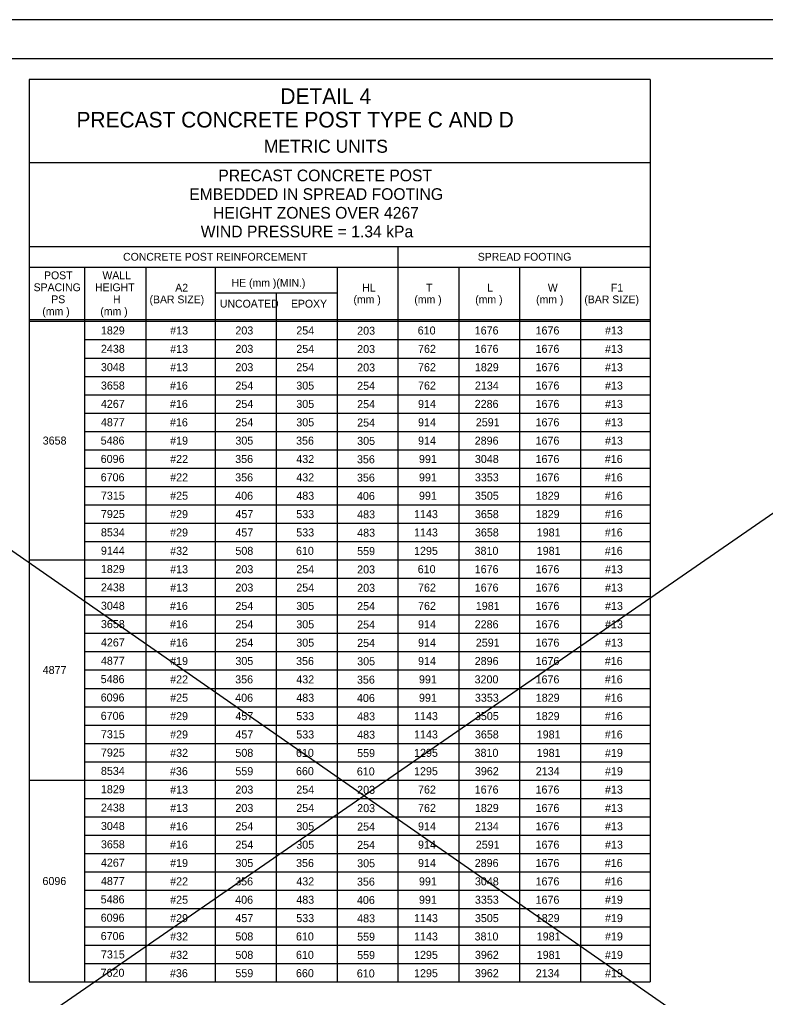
# Model space of a CAD drawing. Extents: x 3351 to 8430, y -3586 to 1457.
# Drawn here: x 7415 to 7700.9, y -2179.4 to -1804.3 of the extents above; entities that cross this region are included whole.
import ezdxf

# ---------------------------------------------------------------- set-up
doc = ezdxf.new("R2010")
doc.units = 0
for name, color, linetype in [('1', 7, 'Continuous'), ('2', 7, 'Continuous'), ('PLT-BNDY', 7, 'Continuous')]:
    doc.layers.add(name, color=color, linetype=linetype)

msp = doc.modelspace()

# ---------------------------------------------------------------- linework, layer by layer
at = {"layer": '1'}
for p, q in [((7144.64, -1822.02), (7933.07, -2370.51)), ((7418.68, -1827.31), (7418.68, -2173.5)), ((7656.68, -1827.31), (7418.68, -1827.31)), ((7656.68, -1827.31), (7656.68, -2173.5)), ((7152.2, -2374.96), (7937.23, -1832.15)), ((7656.68, -1859.31), (7418.68, -1859.31)), ((7418.68, -1891.31), (7656.68, -1891.31)), ((7560.01, -1891.31), (7560.01, -2173.5)), ((7418.68, -1899.31), (7486.68, -1899.31)), ((7418.68, -1899.31), (7656.68, -1899.31)), ((7440.01, -2173.5), (7440.01, -1899.31)), ((7463.34, -1899.31), (7463.34, -2173.5)), ((7490.01, -1899.31), (7490.01, -2173.5)), ((7536.68, -1899.31), (7536.68, -2173.5)), ((7583.34, -1899.31), (7583.34, -2173.5)), ((7606.68, -1899.31), (7606.68, -2173.5)), ((7630.01, -1899.31), (7630.01, -2173.5)), ((7536.71, -1909.31), (7490.05, -1909.31)), ((7513.34, -1909.31), (7513.34, -2173.5)), ((7418.68, -1919.31), (7656.68, -1919.31)), ((7418.68, -1920.06), (7656.68, -1920.06)), ((7476.68, -1923.58), (7476.68, -1923.58)), ((7501.68, -1923.58), (7501.68, -1923.58)), ((7525.01, -1923.58), (7525.01, -1923.58)), ((7548.34, -1923.58), (7548.34, -1923.58)), ((7571.68, -1923.58), (7571.68, -1923.58)), ((7595.01, -1923.58), (7595.01, -1923.58)), ((7618.34, -1923.58), (7618.34, -1923.58)), ((7643.34, -1923.58), (7643.34, -1923.58)), ((7440.01, -1927.1), (7656.68, -1927.1)), ((7440.01, -1934.14), (7656.68, -1934.14)), ((7440.01, -1941.18), (7656.68, -1941.18)), ((7440.01, -1948.22), (7656.68, -1948.22)), ((7440.01, -1955.26), (7656.68, -1955.26)), ((7440.01, -1962.3), (7656.68, -1962.3)), ((7440.01, -1969.34), (7656.68, -1969.34)), ((7440.01, -1976.38), (7656.68, -1976.38)), ((7440.01, -1983.42), (7656.68, -1983.42)), ((7440.01, -1990.46), (7656.68, -1990.46)), ((7440.01, -1997.5), (7656.68, -1997.5)), ((7440.01, -2004.54), (7656.68, -2004.54)), ((7418.68, -2011.58), (7656.68, -2011.58)), ((7418.68, -2011.58), (7656.68, -2011.58)), ((7476.68, -2015.1), (7476.68, -2015.1)), ((7501.68, -2015.1), (7501.68, -2015.1)), ((7525.01, -2015.1), (7525.01, -2015.1)), ((7548.34, -2015.1), (7548.34, -2015.1)), ((7571.68, -2015.1), (7571.68, -2015.1)), ((7595.01, -2015.1), (7595.01, -2015.1)), ((7618.34, -2015.1), (7618.34, -2015.1)), ((7643.34, -2015.1), (7643.34, -2015.1)), ((7440.01, -2018.62), (7656.68, -2018.62)), ((7440.01, -2025.66), (7656.68, -2025.66)), ((7440.01, -2032.7), (7656.68, -2032.7)), ((7440.01, -2039.74), (7656.68, -2039.74)), ((7440.01, -2046.78), (7656.68, -2046.78)), ((7440.01, -2053.82), (7656.68, -2053.82)), ((7440.01, -2060.86), (7656.68, -2060.86)), ((7440.01, -2067.9), (7656.68, -2067.9)), ((7440.01, -2074.94), (7656.68, -2074.94)), ((7440.01, -2081.98), (7656.68, -2081.98)), ((7440.01, -2089.02), (7656.68, -2089.02)), ((7418.68, -2096.06), (7656.68, -2096.06)), ((7476.68, -2099.58), (7476.68, -2099.58)), ((7501.68, -2099.58), (7501.68, -2099.58)), ((7525.01, -2099.58), (7525.01, -2099.58)), ((7548.34, -2099.58), (7548.34, -2099.58)), ((7571.68, -2099.58), (7571.68, -2099.58)), ((7595.01, -2099.58), (7595.01, -2099.58)), ((7618.34, -2099.58), (7618.34, -2099.58)), ((7643.34, -2099.58), (7643.34, -2099.58)), ((7440.01, -2103.1), (7656.68, -2103.1)), ((7440.01, -2110.14), (7656.68, -2110.14)), ((7440.01, -2117.18), (7656.68, -2117.18)), ((7440.01, -2124.22), (7656.68, -2124.22)), ((7440.01, -2131.26), (7656.68, -2131.26)), ((7440.01, -2138.3), (7656.68, -2138.3)), ((7440.01, -2145.34), (7656.68, -2145.34)), ((7440.01, -2152.38), (7656.68, -2152.38)), ((7440.01, -2159.42), (7656.68, -2159.42)), ((7440.01, -2166.46), (7656.68, -2166.46)), ((7418.68, -2173.5), (7656.68, -2173.5))]:
    msp.add_line(p, q, dxfattribs=at)
at = {"layer": '2'}
msp.add_line((7165.34, -1819.31), (7951.34, -1819.31), dxfattribs=at)
at = {"layer": 'PLT-BNDY'}
msp.add_lwpolyline([(7125.34, -1804.31), (7966.34, -1804.31), (7966.34, -2398.31), (7125.34, -2398.31)], close=True, dxfattribs=at)

# ---------------------------------------------------------------- texts
at = {"layer": '1'}
for s, height, p in [('DETAIL 4', 6, (7514.97, -1836.71)), ('PRECAST CONCRETE POST TYPE C AND D', 6, (7436.81, -1845.71)), ('METRIC UNITS', 5, (7508.64, -1855.41)), ('PRECAST CONCRETE POST', 4.5, (7491.19, -1866.36)), ('EMBEDDED IN SPREAD FOOTING', 4.5, (7480.03, -1873.52)), ('HEIGHT ZONES OVER 4267', 4.5, (7489.15, -1880.69)), ('WIND PRESSURE = 1.34 kPa', 4.5, (7484.44, -1887.86)), ('CONCRETE POST REINFORCEMENT', 3, (7454.68, -1896.81)), ('SPREAD FOOTING', 3, (7590.63, -1896.81)), ('POST', 3, (7424.4, -1903.91)), ('WALL', 3, (7446.76, -1903.91)), ('SPACING', 3, (7420.4, -1908.51)), ('HEIGHT', 3, (7443.93, -1908.51)), ('A2', 3, (7474.67, -1908.67)), ('HE (mm )(MIN.)', 3, (7496.27, -1906.8)), ('HL', 3, (7546.31, -1908.67)), ('T', 3, (7570.82, -1908.67)), ('L', 3, (7594.27, -1908.67)), ('W', 3, (7617.48, -1908.67)), ('F1', 3, (7641.64, -1908.67)), ('PS', 3, (7427.16, -1913.11)), ('H', 3, (7450.81, -1913.11)), ('(BAR SIZE)', 3, (7464.81, -1913.17)), ('UNCOATED', 3, (7491.8, -1914.8)), ('EPOXY', 3, (7519.03, -1914.8)), ('(mm )', 3, (7542.98, -1913.17)), ('(mm )', 3, (7566.31, -1913.17)), ('(mm )', 3, (7589.65, -1913.17)), ('(mm )', 3, (7612.98, -1913.17)), ('(BAR SIZE)', 3, (7631.47, -1913.17)), ('(mm )', 3, (7423.73, -1917.71)), ('(mm )', 3, (7445.96, -1917.71)), ('1829', 3.07, (7446.18, -1925.11)), ('#13', 3.07, (7472.73, -1925.11)), ('203', 3.07, (7497.73, -1925.11)), ('254', 3.07, (7521.07, -1925.11)), ('203', 3.07, (7544.4, -1925.21)), ('610', 3.07, (7567.6, -1925.11)), ('1676', 3.07, (7589.45, -1925.11)), ('1676', 3.07, (7612.78, -1925.11)), ('#13', 3.07, (7639.4, -1925.11)), ('2438', 3.07, (7446.19, -1932.15)), ('#13', 3.07, (7472.73, -1932.16)), ('203', 3.07, (7497.73, -1932.16)), ('254', 3.07, (7521.07, -1932.16)), ('203', 3.07, (7544.4, -1932.25)), ('762', 3.07, (7567.73, -1932.16)), ('1676', 3.07, (7589.45, -1932.16)), ('1676', 3.07, (7612.78, -1932.16)), ('#13', 3.07, (7639.4, -1932.16)), ('3048', 3.07, (7446.19, -1939.19)), ('#13', 3.07, (7472.73, -1939.2)), ('203', 3.07, (7497.73, -1939.2)), ('254', 3.07, (7521.07, -1939.2)), ('203', 3.07, (7544.4, -1939.3)), ('762', 3.07, (7567.73, -1939.2)), ('1829', 3.07, (7589.52, -1939.2)), ('1676', 3.07, (7612.78, -1939.2)), ('#13', 3.07, (7639.4, -1939.2)), ('3658', 3.07, (7446.19, -1946.23)), ('#16', 3.07, (7472.65, -1946.25)), ('254', 3.07, (7497.73, -1946.25)), ('305', 3.07, (7521.07, -1946.25)), ('762', 3.07, (7567.73, -1946.25)), ('2134', 3.07, (7589.53, -1946.25)), ('1676', 3.07, (7612.78, -1946.25)), ('#13', 3.07, (7639.4, -1946.25)), ('254', 3.07, (7544.4, -1946.34)), ('4267', 3.07, (7446.19, -1953.27)), ('#16', 3.07, (7472.65, -1953.29)), ('254', 3.07, (7497.73, -1953.29)), ('305', 3.07, (7521.07, -1953.29)), ('254', 3.07, (7544.4, -1953.38)), ('914', 3.07, (7567.73, -1953.29)), ('2286', 3.07, (7589.45, -1953.29)), ('1676', 3.07, (7612.78, -1953.29)), ('#13', 3.07, (7639.4, -1953.29)), ('4877', 3.07, (7446.19, -1960.31)), ('#16', 3.07, (7472.65, -1960.34)), ('254', 3.07, (7497.73, -1960.34)), ('305', 3.07, (7521.07, -1960.34)), ('254', 3.07, (7544.4, -1960.43)), ('914', 3.07, (7567.73, -1960.34)), ('2591', 3.07, (7589.88, -1960.34)), ('1676', 3.07, (7612.78, -1960.34)), ('#13', 3.07, (7639.4, -1960.34)), ('3658', 3.07, (7423.87, -1967.35)), ('5486', 3.07, (7446.1, -1967.35)), ('#19', 3.07, (7472.72, -1967.38)), ('305', 3.07, (7497.73, -1967.38)), ('356', 3.07, (7520.98, -1967.38)), ('305', 3.07, (7544.4, -1967.47)), ('914', 3.07, (7567.73, -1967.38)), ('2896', 3.07, (7589.45, -1967.38)), ('1676', 3.07, (7612.78, -1967.38)), ('#13', 3.07, (7639.4, -1967.38)), ('6096', 3.07, (7446.1, -1974.39)), ('#22', 3.07, (7472.73, -1974.42)), ('356', 3.07, (7497.65, -1974.42)), ('432', 3.07, (7521.07, -1974.42)), ('356', 3.07, (7544.32, -1974.52)), ('991', 3.07, (7568.09, -1974.42)), ('3048', 3.07, (7589.53, -1974.42)), ('1676', 3.07, (7612.78, -1974.42)), ('#16', 3.07, (7639.32, -1974.42)), ('6706', 3.07, (7446.1, -1981.43)), ('#22', 3.07, (7472.73, -1981.47)), ('356', 3.07, (7497.65, -1981.47)), ('432', 3.07, (7521.07, -1981.47)), ('356', 3.07, (7544.32, -1981.56)), ('991', 3.07, (7568.09, -1981.47)), ('3353', 3.07, (7589.53, -1981.47)), ('1676', 3.07, (7612.78, -1981.47)), ('#16', 3.07, (7639.32, -1981.47)), ('7315', 3.07, (7446.19, -1988.47)), ('#25', 3.07, (7472.73, -1988.51)), ('406', 3.07, (7497.65, -1988.51)), ('483', 3.07, (7521.07, -1988.51)), ('406', 3.07, (7544.32, -1988.61)), ('991', 3.07, (7568.09, -1988.51)), ('3505', 3.07, (7589.53, -1988.51)), ('1829', 3.07, (7612.85, -1988.51)), ('#16', 3.07, (7639.32, -1988.51)), ('7925', 3.07, (7446.19, -1995.51)), ('#29', 3.07, (7472.72, -1995.56)), ('457', 3.07, (7497.73, -1995.56)), ('533', 3.07, (7521.07, -1995.56)), ('483', 3.07, (7544.4, -1995.65)), ('1143', 3.07, (7566.2, -1995.56)), ('3658', 3.07, (7589.53, -1995.56)), ('1829', 3.07, (7612.85, -1995.56)), ('#16', 3.07, (7639.32, -1995.56)), ('8534', 3.07, (7446.19, -2002.55)), ('#29', 3.07, (7472.72, -2002.6)), ('457', 3.07, (7497.73, -2002.6)), ('533', 3.07, (7521.07, -2002.6)), ('483', 3.07, (7544.4, -2002.7)), ('1143', 3.07, (7566.2, -2002.6)), ('3658', 3.07, (7589.53, -2002.6)), ('1981', 3.07, (7613.22, -2002.6)), ('#16', 3.07, (7639.32, -2002.6)), ('9144', 3.07, (7446.19, -2009.59)), ('#32', 3.07, (7472.73, -2009.65)), ('508', 3.07, (7497.73, -2009.65)), ('610', 3.07, (7520.94, -2009.65)), ('559', 3.07, (7544.39, -2009.74)), ('1295', 3.07, (7566.2, -2009.65)), ('3810', 3.07, (7589.4, -2009.65)), ('1981', 3.07, (7613.22, -2009.65)), ('#16', 3.07, (7639.32, -2009.65)), ('1829', 3.07, (7446.18, -2016.63)), ('#13', 3.07, (7472.73, -2016.69)), ('203', 3.07, (7497.73, -2016.69)), ('254', 3.07, (7521.07, -2016.69)), ('203', 3.07, (7544.4, -2016.79)), ('610', 3.07, (7567.6, -2016.69)), ('1676', 3.07, (7589.45, -2016.69)), ('1676', 3.07, (7612.78, -2016.69)), ('#13', 3.07, (7639.4, -2016.69)), ('2438', 3.07, (7446.19, -2023.67)), ('#13', 3.07, (7472.73, -2023.74)), ('203', 3.07, (7497.73, -2023.74)), ('254', 3.07, (7521.07, -2023.74)), ('203', 3.07, (7544.4, -2023.83)), ('762', 3.07, (7567.73, -2023.74)), ('1676', 3.07, (7589.45, -2023.74)), ('1676', 3.07, (7612.78, -2023.74)), ('#13', 3.07, (7639.4, -2023.74)), ('3048', 3.07, (7446.19, -2030.71)), ('#16', 3.07, (7472.65, -2030.78)), ('254', 3.07, (7497.73, -2030.78)), ('305', 3.07, (7521.07, -2030.78)), ('254', 3.07, (7544.4, -2030.87)), ('762', 3.07, (7567.73, -2030.78)), ('1981', 3.07, (7589.88, -2030.78)), ('1676', 3.07, (7612.78, -2030.78)), ('#13', 3.07, (7639.4, -2030.78)), ('3658', 3.07, (7446.19, -2037.75)), ('#16', 3.07, (7472.65, -2037.82)), ('254', 3.07, (7497.73, -2037.82)), ('305', 3.07, (7521.07, -2037.82)), ('254', 3.07, (7544.4, -2037.92)), ('914', 3.07, (7567.73, -2037.82)), ('2286', 3.07, (7589.45, -2037.82)), ('1676', 3.07, (7612.78, -2037.82)), ('#13', 3.07, (7639.4, -2037.82)), ('4267', 3.07, (7446.19, -2044.79)), ('#16', 3.07, (7472.65, -2044.87)), ('254', 3.07, (7497.73, -2044.87)), ('305', 3.07, (7521.07, -2044.87)), ('254', 3.07, (7544.4, -2044.96)), ('914', 3.07, (7567.73, -2044.87)), ('2591', 3.07, (7589.88, -2044.87)), ('1676', 3.07, (7612.78, -2044.87)), ('#13', 3.07, (7639.4, -2044.87)), ('4877', 3.07, (7446.19, -2051.83)), ('#19', 3.07, (7472.72, -2051.91)), ('305', 3.07, (7497.73, -2051.91)), ('356', 3.07, (7520.98, -2051.91)), ('305', 3.07, (7544.4, -2052.01)), ('914', 3.07, (7567.73, -2051.91)), ('2896', 3.07, (7589.45, -2051.91)), ('1676', 3.07, (7612.78, -2051.91)), ('#16', 3.07, (7639.32, -2051.91)), ('4877', 3.07, (7423.87, -2055.35)), ('5486', 3.07, (7446.1, -2058.87)), ('#22', 3.07, (7472.73, -2058.96)), ('356', 3.07, (7497.65, -2058.96)), ('432', 3.07, (7521.07, -2058.96)), ('356', 3.07, (7544.32, -2059.05)), ('991', 3.07, (7568.09, -2058.96)), ('3200', 3.07, (7589.4, -2058.96)), ('1676', 3.07, (7612.78, -2058.96)), ('#16', 3.07, (7639.32, -2058.96)), ('6096', 3.07, (7446.1, -2065.91)), ('#25', 3.07, (7472.73, -2066)), ('406', 3.07, (7497.65, -2066)), ('483', 3.07, (7521.07, -2066)), ('406', 3.07, (7544.32, -2066.1)), ('991', 3.07, (7568.09, -2066)), ('3353', 3.07, (7589.53, -2066)), ('1829', 3.07, (7612.85, -2066)), ('#16', 3.07, (7639.32, -2066)), ('6706', 3.07, (7446.1, -2072.95)), ('#29', 3.07, (7472.72, -2073.05)), ('457', 3.07, (7497.73, -2073.05)), ('533', 3.07, (7521.07, -2073.05)), ('483', 3.07, (7544.4, -2073.14)), ('1143', 3.07, (7566.2, -2073.05)), ('3505', 3.07, (7589.53, -2073.05)), ('1829', 3.07, (7612.85, -2073.05)), ('#16', 3.07, (7639.32, -2073.05)), ('7315', 3.07, (7446.19, -2079.99)), ('#29', 3.07, (7472.72, -2080.09)), ('457', 3.07, (7497.73, -2080.09)), ('533', 3.07, (7521.07, -2080.09)), ('483', 3.07, (7544.4, -2080.19)), ('1143', 3.07, (7566.2, -2080.09)), ('3658', 3.07, (7589.53, -2080.09)), ('1981', 3.07, (7613.22, -2080.09)), ('#16', 3.07, (7639.32, -2080.09)), ('7925', 3.07, (7446.19, -2087.03)), ('#32', 3.07, (7472.73, -2087.14)), ('508', 3.07, (7497.73, -2087.14)), ('610', 3.07, (7520.94, -2087.14)), ('559', 3.07, (7544.39, -2087.23)), ('1295', 3.07, (7566.2, -2087.14)), ('3810', 3.07, (7589.4, -2087.14)), ('1981', 3.07, (7613.22, -2087.14)), ('#19', 3.07, (7639.39, -2087.14)), ('8534', 3.07, (7446.19, -2094.07)), ('#36', 3.07, (7472.65, -2094.18)), ('559', 3.07, (7497.72, -2094.18)), ('660', 3.07, (7520.94, -2094.18)), ('610', 3.07, (7544.27, -2094.27)), ('1295', 3.07, (7566.2, -2094.18)), ('3962', 3.07, (7589.53, -2094.18)), ('2134', 3.07, (7612.87, -2094.18)), ('#19', 3.07, (7639.39, -2094.18)), ('1829', 3.07, (7446.18, -2101.11)), ('#13', 3.07, (7472.73, -2101.22)), ('203', 3.07, (7497.73, -2101.22)), ('254', 3.07, (7521.07, -2101.22)), ('203', 3.07, (7544.4, -2101.32)), ('762', 3.07, (7567.73, -2101.22)), ('1676', 3.07, (7589.45, -2101.22)), ('1676', 3.07, (7612.78, -2101.22)), ('#13', 3.07, (7639.4, -2101.22)), ('2438', 3.07, (7446.19, -2108.15)), ('#13', 3.07, (7472.73, -2108.27)), ('203', 3.07, (7497.73, -2108.27)), ('254', 3.07, (7521.07, -2108.27)), ('203', 3.07, (7544.4, -2108.36)), ('762', 3.07, (7567.73, -2108.27)), ('1829', 3.07, (7589.52, -2108.27)), ('1676', 3.07, (7612.78, -2108.27)), ('#13', 3.07, (7639.4, -2108.27)), ('3048', 3.07, (7446.19, -2115.19)), ('#16', 3.07, (7472.65, -2115.31)), ('254', 3.07, (7497.73, -2115.31)), ('305', 3.07, (7521.07, -2115.31)), ('254', 3.07, (7544.4, -2115.41)), ('914', 3.07, (7567.73, -2115.31)), ('2134', 3.07, (7589.53, -2115.31)), ('1676', 3.07, (7612.78, -2115.31)), ('#13', 3.07, (7639.4, -2115.31)), ('3658', 3.07, (7446.19, -2122.23)), ('#16', 3.07, (7472.65, -2122.36)), ('254', 3.07, (7497.73, -2122.36)), ('305', 3.07, (7521.07, -2122.36)), ('254', 3.07, (7544.4, -2122.45)), ('914', 3.07, (7567.73, -2122.36)), ('2591', 3.07, (7589.88, -2122.36)), ('1676', 3.07, (7612.78, -2122.36)), ('#13', 3.07, (7639.4, -2122.36)), ('4267', 3.07, (7446.19, -2129.27)), ('#19', 3.07, (7472.72, -2129.4)), ('305', 3.07, (7497.73, -2129.4)), ('356', 3.07, (7520.98, -2129.4)), ('305', 3.07, (7544.4, -2129.5)), ('914', 3.07, (7567.73, -2129.4)), ('2896', 3.07, (7589.45, -2129.4)), ('1676', 3.07, (7612.78, -2129.4)), ('#16', 3.07, (7639.32, -2129.4)), ('6096', 3.07, (7423.78, -2136.31)), ('4877', 3.07, (7446.19, -2136.31)), ('#22', 3.07, (7472.73, -2136.45)), ('356', 3.07, (7497.65, -2136.45)), ('432', 3.07, (7521.07, -2136.45)), ('356', 3.07, (7544.32, -2136.54)), ('991', 3.07, (7568.09, -2136.45)), ('3048', 3.07, (7589.53, -2136.45)), ('1676', 3.07, (7612.78, -2136.45)), ('#16', 3.07, (7639.32, -2136.45)), ('5486', 3.07, (7446.1, -2143.35)), ('#25', 3.07, (7472.73, -2143.49)), ('406', 3.07, (7497.65, -2143.49)), ('483', 3.07, (7521.07, -2143.49)), ('406', 3.07, (7544.32, -2143.59)), ('991', 3.07, (7568.09, -2143.49)), ('3353', 3.07, (7589.53, -2143.49)), ('1676', 3.07, (7612.78, -2143.49)), ('#19', 3.07, (7639.39, -2143.49)), ('6096', 3.07, (7446.1, -2150.39)), ('#29', 3.07, (7472.72, -2150.54)), ('457', 3.07, (7497.73, -2150.54)), ('533', 3.07, (7521.07, -2150.54)), ('483', 3.07, (7544.4, -2150.63)), ('1143', 3.07, (7566.2, -2150.54)), ('3505', 3.07, (7589.53, -2150.54)), ('1829', 3.07, (7612.85, -2150.54)), ('#19', 3.07, (7639.39, -2150.54)), ('6706', 3.07, (7446.1, -2157.43)), ('#32', 3.07, (7472.73, -2157.58)), ('508', 3.07, (7497.73, -2157.58)), ('610', 3.07, (7520.94, -2157.58)), ('559', 3.07, (7544.39, -2157.67)), ('1143', 3.07, (7566.2, -2157.58)), ('3810', 3.07, (7589.4, -2157.58)), ('1981', 3.07, (7613.22, -2157.58)), ('#19', 3.07, (7639.39, -2157.58)), ('7315', 3.07, (7446.19, -2164.47)), ('#32', 3.07, (7472.73, -2164.63)), ('508', 3.07, (7497.73, -2164.63)), ('610', 3.07, (7520.94, -2164.63)), ('559', 3.07, (7544.39, -2164.72)), ('1295', 3.07, (7566.2, -2164.63)), ('3962', 3.07, (7589.53, -2164.63)), ('1981', 3.07, (7613.22, -2164.63)), ('#19', 3.07, (7639.39, -2164.63)), ('7620', 3.07, (7446.06, -2171.51)), ('#36', 3.07, (7472.65, -2171.67)), ('559', 3.07, (7497.72, -2171.67)), ('660', 3.07, (7520.94, -2171.67)), ('610', 3.07, (7544.27, -2171.76)), ('1295', 3.07, (7566.2, -2171.67)), ('3962', 3.07, (7589.53, -2171.67)), ('2134', 3.07, (7612.87, -2171.67)), ('#19', 3.07, (7639.39, -2171.67))]:
    msp.add_text(s, height=height, dxfattribs=at).set_placement(p)

doc.saveas('drawing.dxf')
